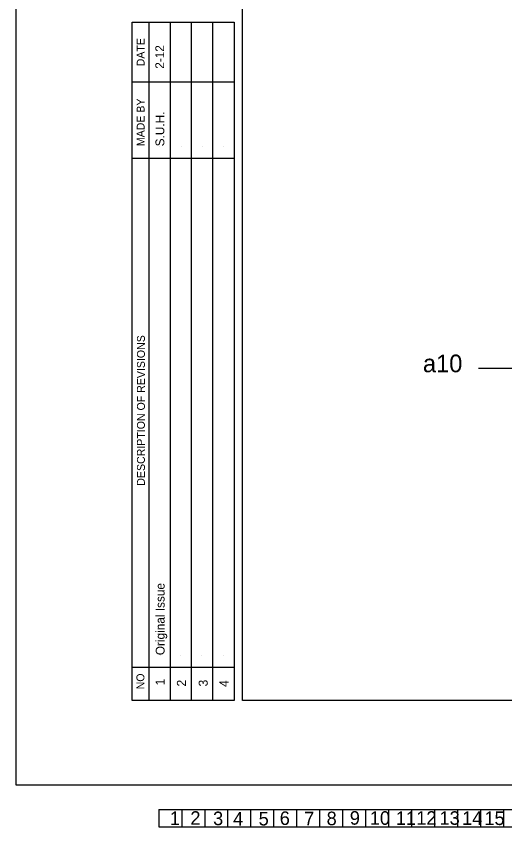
# Model space of a CAD drawing. Extents: x -0.08 to 2.83, y -0.03 to 1.92.
# Drawn here: x 0 to 0.36, y -0.031 to 0.567 of the extents above; entities that cross this region are included whole.
import ezdxf

# ---------------------------------------------------------------- set-up
doc = ezdxf.new("R2010")
doc.units = 0
for name, color, linetype in [('1', 7, 'Continuous'), ('10', 7, 'Continuous'), ('11', 7, 'Continuous'), ('12', 7, 'Continuous'), ('13', 7, 'Continuous'), ('14', 7, 'Continuous'), ('15', 7, 'Continuous'), ('2', 7, 'Continuous'), ('3', 7, 'Continuous'), ('4', 7, 'Continuous'), ('5', 7, 'Continuous'), ('55', 7, 'Continuous'), ('57', 7, 'Continuous'), ('6', 7, 'Continuous'), ('62', 7, 'Continuous'), ('63', 7, 'Continuous'), ('7', 7, 'Continuous'), ('8', 7, 'Continuous'), ('9', 7, 'Continuous')]:
    doc.layers.add(name, color=color, linetype=linetype)

msp = doc.modelspace()

# ---------------------------------------------------------------- linework, layer by layer
at = {"layer": '55'}
msp.add_line((0.34063, 0.3074), (0.43662, 0.3074), dxfattribs=at)
at = {"layer": '62'}
for p, q in [((0.10585, 0.47101), (0.10585, 0.47101)), ((0.12188, 0.47101), (0.12188, 0.47101)), ((0.13719, 0.47101), (0.13719, 0.47101)), ((0.15252, 0.47101), (0.15252, 0.47101)), ((0.10603, 0.09579), (0.10603, 0.09579)), ((0.15304, 0.09579), (0.15304, 0.09579)), ((0.121, 0.09544), (0.121, 0.09544)), ((0.13668, 0.09544), (0.13668, 0.09544)), ((0.10494, -0.01804), (1.17174, -0.01804)), ((0.10494, -0.01804), (0.10494, -0.03074)), ((0.12188, -0.01804), (0.12188, -0.03074)), ((0.13881, -0.01804), (0.13881, -0.03074)), ((0.15574, -0.01804), (0.15574, -0.03074)), ((0.17267, -0.01804), (0.17267, -0.03074)), ((0.18961, -0.01804), (0.18961, -0.03074)), ((0.20654, -0.01804), (0.20654, -0.03074)), ((0.22348, -0.01804), (0.22348, -0.03074)), ((0.24041, -0.01804), (0.24041, -0.03074)), ((0.25734, -0.01804), (0.25734, -0.03074)), ((0.27427, -0.01804), (0.27427, -0.03074)), ((0.29121, -0.01804), (0.29121, -0.03074)), ((0.30814, -0.01804), (0.30814, -0.03074)), ((0.32508, -0.01804), (0.32508, -0.03074)), ((0.34201, -0.01804), (0.34201, -0.03074)), ((0.35894, -0.01804), (0.35894, -0.03074)), ((0.10494, -0.03074), (1.17174, -0.03074))]:
    msp.add_line(p, q, dxfattribs=at)
at = {"layer": '63'}
for p, q in [((0, 0), (0, 1.83333)), ((0.08543, 0.06244), (0.08543, 0.56244)), ((0.08543, 0.56244), (0.16043, 0.56244)), ((0.09792, 0.06244), (0.09792, 0.56244)), ((0.11353, 0.06259), (0.11353, 0.56244)), ((0.12914, 0.06275), (0.12914, 0.56244)), ((0.14474, 0.0629), (0.14474, 0.56244)), ((0.16043, 0.56244), (0.16043, 0.06244)), ((0.08543, 0.51859), (0.16043, 0.51859)), ((0.08543, 0.46218), (0.16043, 0.46218)), ((0.08543, 0.08707), (0.16043, 0.08707)), ((0.16043, 0.06244), (0.08543, 0.06244)), ((2.83333, 0), (0, 0))]:
    msp.add_line(p, q, dxfattribs=at)
msp.add_lwpolyline([(0.16668, 0.06244), (0.16668, 1.77077), (2.72918, 1.77077), (2.72918, 0.10411), (2.56251, 0.10411), (2.56251, 0.14578), (2.07387, 0.14578), (2.07387, 0.06244)], close=True, dxfattribs=at)

# ---------------------------------------------------------------- texts
at = {"layer": '1'}
msp.add_text('1', height=0.01, rotation=360, dxfattribs=at).set_placement((0.11316, -0.02944))
at = {"layer": '10'}
msp.add_text('10', height=0.01, rotation=360, dxfattribs=at).set_placement((0.26046, -0.02928))
at = {"layer": '11'}
msp.add_text('11', height=0.01, rotation=360, dxfattribs=at).set_placement((0.2796, -0.02937))
at = {"layer": '12'}
msp.add_text('12', height=0.01, rotation=360, dxfattribs=at).set_placement((0.29469, -0.02925))
at = {"layer": '13'}
msp.add_text('13', height=0.01, rotation=360, dxfattribs=at).set_placement((0.31181, -0.02928))
at = {"layer": '14'}
msp.add_text('14', height=0.01, rotation=360, dxfattribs=at).set_placement((0.32844, -0.02939))
at = {"layer": '15'}
msp.add_text('15', height=0.01, rotation=360, dxfattribs=at).set_placement((0.34488, -0.02946))
at = {"layer": '2'}
msp.add_text('2', height=0.01, rotation=360, dxfattribs=at).set_placement((0.12828, -0.02928))
at = {"layer": '3'}
msp.add_text('3', height=0.01, rotation=360, dxfattribs=at).set_placement((0.145, -0.02955))
at = {"layer": '4'}
msp.add_text('4', height=0.01, rotation=360, dxfattribs=at).set_placement((0.15973, -0.02984))
at = {"layer": '5'}
msp.add_text('5', height=0.01, rotation=360, dxfattribs=at).set_placement((0.17858, -0.02977))
at = {"layer": '57'}
msp.add_text('a10', height=0.013017, dxfattribs=at).set_placement((0.29959, 0.30441))
at = {"layer": '6'}
msp.add_text('6', height=0.01, rotation=360, dxfattribs=at).set_placement((0.19409, -0.02938))
at = {"layer": '62'}
for s, height, p in [(' 2-12', 0.006508, (0.10896, 0.52578)), ('S.U.H.  ', 0.006508, (0.1091, 0.47101)), ('Original Issue                                                   ', 0.0065084, (0.10928, 0.09579))]:
    msp.add_text(s, height=height, rotation=90, dxfattribs=at).set_placement(p)
at = {"layer": '63'}
for s, height, p in [('DATE', 0.005833, (0.09454, 0.53)), ('MADE BY', 0.005833, (0.09454, 0.47113)), ('DESCRIPTION OF REVISIONS', 0.0058333, (0.09477, 0.22076)), ('NO', 0.005833, (0.09439, 0.07059)), ('1', 0.00667, (0.10936, 0.0735)), ('2', 0.00667, (0.12503, 0.07272)), ('3', 0.00667, (0.14105, 0.07272)), ('4', 0.00667, (0.15638, 0.07237))]:
    msp.add_text(s, height=height, rotation=90, dxfattribs=at).set_placement(p)
at = {"layer": '7'}
msp.add_text('7', height=0.01, rotation=360, dxfattribs=at).set_placement((0.21211, -0.02964))
at = {"layer": '8'}
msp.add_text('8', height=0.01, rotation=360, dxfattribs=at).set_placement((0.22865, -0.02958))
at = {"layer": '9'}
msp.add_text('9', height=0.01, rotation=360, dxfattribs=at).set_placement((0.24573, -0.02921))

doc.saveas('drawing.dxf')
